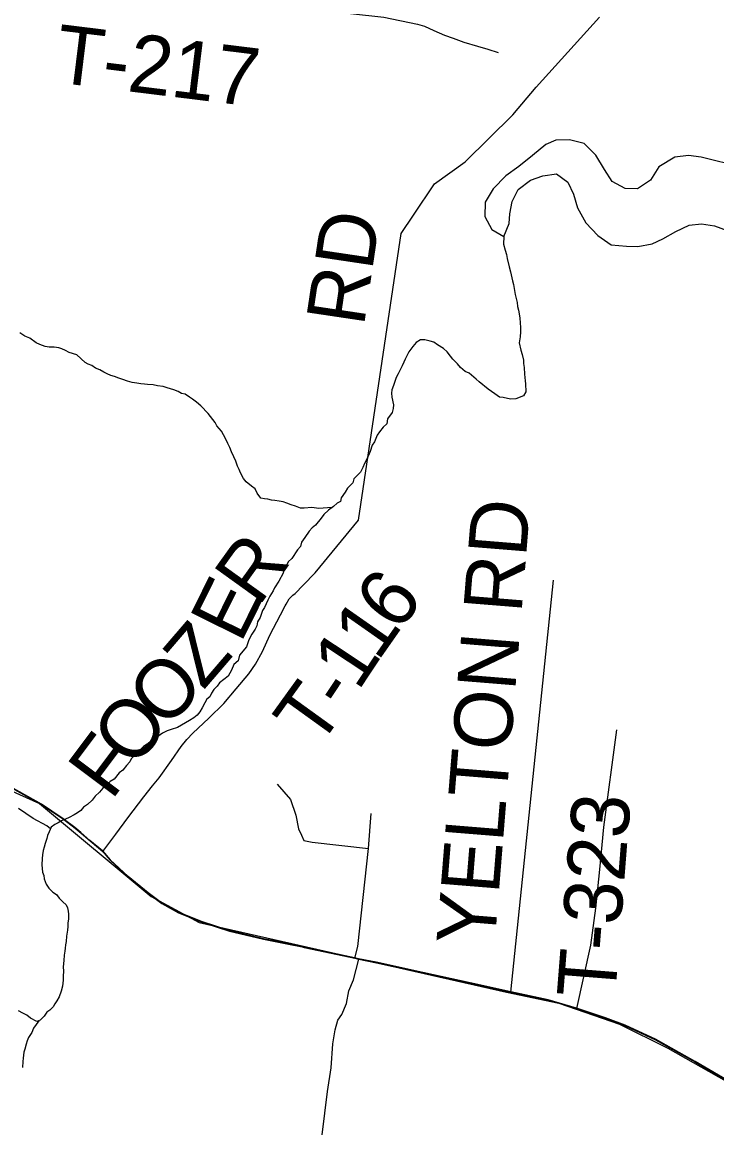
# Model space of a CAD drawing. Extents: x 0 to 39.3, y -3.9 to 22.
# Drawn here: x 6.949 to 7.624, y 16.679 to 17.777 of the extents above; entities that cross this region are included whole.
import ezdxf

# ---------------------------------------------------------------- set-up
doc = ezdxf.new("R2010")
doc.units = 0
for name, color, linetype in [('GM_X_Corporation', 7, 'Continuous'), ('GM_X_Major_Lake', 7, 'Continuous'), ('GM_X_Minor_River', 7, 'Continuous'), ('GM_X_Rail_Line', 7, 'Continuous'), ('GM_X_State_Route', 7, 'Continuous'), ('GM_X_Township_Road', 7, 'Continuous'), ('GM_X_Township_Road_Text', 7, 'Continuous')]:
    doc.layers.add(name, color=color, linetype=linetype)

msp = doc.modelspace()

# ---------------------------------------------------------------- linework, layer by layer
at = {"layer": 'GM_X_Corporation'}
for points in [[(6.9385, 17.0327), (6.9679, 17.0164), (6.9891, 17.0021), (7.0005, 16.9934), (7.0062, 16.9886), (7.0151, 16.9809), (7.0274, 16.9707), (7.0348, 16.962), (7.0525, 16.9457), (7.0718, 16.9299), (7.0848, 16.9201), (7.1011, 16.9111), (7.1248, 16.9016), (7.1506, 16.8932), (7.1841, 16.8853), (7.2066, 16.881), (7.2216, 16.8777), (7.2729, 16.8668), (7.2768, 16.8658), (7.294, 16.8623), (7.3392, 16.8523), (7.3929, 16.8408), (7.4249, 16.8337), (7.4386, 16.8306), (7.4615, 16.8258), (7.4891, 16.8177), (7.5171, 16.8082), (7.5364, 16.801), (7.5658, 16.7873), (7.6047, 16.7657), (7.6579, 16.7347)], [(7.6579, 16.7347), (7.6047, 16.7657), (7.5658, 16.7873), (7.5364, 16.801), (7.5171, 16.8082), (7.4891, 16.8177), (7.4615, 16.8258), (7.4386, 16.8306), (7.4249, 16.8337), (7.3929, 16.8408), (7.3392, 16.8523), (7.294, 16.8623), (7.2768, 16.8658), (7.2729, 16.8668), (7.2216, 16.8777), (7.2066, 16.881), (7.1841, 16.8853), (7.1506, 16.8932), (7.1248, 16.9016), (7.1011, 16.9111), (7.0848, 16.9201), (7.0718, 16.9299), (7.0525, 16.9457), (7.0348, 16.962), (7.0274, 16.9707), (7.0151, 16.9809), (7.0062, 16.9886), (7.0005, 16.9934), (6.9891, 17.0021), (6.9679, 17.0164), (6.9385, 17.0327)]]:
    msp.add_lwpolyline(points, dxfattribs=at)
at = {"layer": 'GM_X_Major_Lake'}
msp.add_lwpolyline([(7.6366, 17.6396), (7.6233, 17.6428), (7.6105, 17.6461), (7.5979, 17.6478), (7.5846, 17.6461), (7.5693, 17.6369), (7.5611, 17.6237), (7.5484, 17.6155), (7.5363, 17.6157), (7.5238, 17.6224), (7.5161, 17.6343), (7.5079, 17.6481), (7.4963, 17.6594), (7.4823, 17.663), (7.4687, 17.6629), (7.4591, 17.6585), (7.446, 17.6477), (7.4329, 17.6372), (7.4202, 17.6279), (7.4079, 17.6152), (7.4001, 17.6024), (7.3998, 17.5883), (7.4065, 17.5757), (7.4181, 17.569), (7.4233, 17.5815), (7.4242, 17.591), (7.4263, 17.6031), (7.4322, 17.6148), (7.4441, 17.6237), (7.4563, 17.6281), (7.4696, 17.6298), (7.4805, 17.622), (7.486, 17.6101), (7.49, 17.5967), (7.4981, 17.5822), (7.5097, 17.5698), (7.5228, 17.5608), (7.5376, 17.5594), (7.5487, 17.5593), (7.5627, 17.5617), (7.5731, 17.5668), (7.5857, 17.5739), (7.5988, 17.5801), (7.6106, 17.5814), (7.6234, 17.5793), (7.6382, 17.5738)], dxfattribs=at)
at = {"layer": 'GM_X_Minor_River'}
for points in [[(7.4181, 17.569), (7.418, 17.5616), (7.4195, 17.5555), (7.4209, 17.5513), (7.4216, 17.5475), (7.4234, 17.5395), (7.4248, 17.5345), (7.4266, 17.5257), (7.4276, 17.5223), (7.4294, 17.5124), (7.4311, 17.5047), (7.4315, 17.5009), (7.4325, 17.4971), (7.4332, 17.4936), (7.4339, 17.4895), (7.4345, 17.4803), (7.4345, 17.4761), (7.434, 17.4712), (7.4331, 17.4655), (7.4349, 17.4582), (7.436, 17.454), (7.4374, 17.4487), (7.4374, 17.4453), (7.4381, 17.4414), (7.4383, 17.435), (7.439, 17.4285), (7.4393, 17.4254), (7.4396, 17.4178), (7.4372, 17.4137), (7.4299, 17.4108), (7.4246, 17.4105), (7.4174, 17.4121), (7.414, 17.4126), (7.4095, 17.4157), (7.4031, 17.4204), (7.3941, 17.4274), (7.3911, 17.4301), (7.3844, 17.4359), (7.3806, 17.4375), (7.3761, 17.4414), (7.3731, 17.4449), (7.3686, 17.4495), (7.3664, 17.4526), (7.363, 17.4565), (7.3593, 17.4599), (7.3537, 17.4635), (7.3499, 17.4662), (7.3465, 17.467), (7.3412, 17.4682), (7.337, 17.4683), (7.3328, 17.4657), (7.3297, 17.462), (7.3258, 17.4567), (7.3222, 17.4496), (7.3207, 17.4465), (7.3191, 17.4431), (7.3152, 17.4352), (7.3132, 17.4318), (7.3108, 17.4239), (7.3092, 17.4197), (7.3088, 17.4163), (7.3091, 17.4125), (7.3108, 17.4049), (7.3104, 17.4015), (7.3096, 17.3977), (7.3049, 17.3913), (7.3041, 17.3864), (7.3006, 17.3834), (7.2971, 17.3789), (7.2948, 17.3755), (7.2924, 17.3691), (7.29, 17.3657), (7.288, 17.3596), (7.2849, 17.3521), (7.2825, 17.3479), (7.2809, 17.3442), (7.2786, 17.3396), (7.272, 17.3329), (7.2712, 17.3291), (7.2661, 17.3239), (7.2638, 17.3201), (7.2599, 17.3145), (7.2591, 17.3111), (7.256, 17.3092), (7.2522, 17.3062), (7.2475, 17.3025), (7.2429, 17.2984), (7.2402, 17.2947), (7.2347, 17.2879), (7.2317, 17.2853), (7.2286, 17.2819), (7.2243, 17.2759)], [(7.2508, 17.3052), (7.2381, 17.3042), (7.2312, 17.3051), (7.2236, 17.3045), (7.2202, 17.3045), (7.2153, 17.3065), (7.2111, 17.3077), (7.207, 17.3093), (7.2032, 17.3105), (7.1994, 17.3113), (7.1952, 17.3118), (7.1918, 17.3122), (7.1884, 17.3131), (7.185, 17.3135), (7.1816, 17.3143), (7.1779, 17.319), (7.176, 17.3232), (7.1723, 17.3259), (7.1674, 17.3302), (7.1648, 17.3333), (7.1618, 17.339), (7.1604, 17.3421), (7.1589, 17.3455), (7.1571, 17.3501), (7.1553, 17.3543), (7.1531, 17.3593), (7.1512, 17.3635), (7.1494, 17.3674), (7.1472, 17.3724), (7.1431, 17.3793), (7.1387, 17.3847), (7.1372, 17.3878), (7.1301, 17.3966), (7.123, 17.404), (7.1189, 17.4075), (7.1151, 17.4106), (7.1121, 17.4125), (7.108, 17.4153), (7.1042, 17.4161), (7.1012, 17.4181), (7.0967, 17.4197), (7.0936, 17.4205), (7.0902, 17.4217), (7.0865, 17.4229), (7.0808, 17.4237), (7.0766, 17.4246), (7.0713, 17.4247), (7.0682, 17.4251), (7.0648, 17.4255), (7.0607, 17.426), (7.0561, 17.4268), (7.0516, 17.4281), (7.047, 17.4297), (7.0433, 17.4309), (7.0391, 17.4325), (7.0353, 17.4337), (7.0319, 17.4352), (7.0285, 17.4368), (7.0248, 17.4392), (7.0206, 17.4408), (7.0169, 17.4435), (7.0135, 17.4447), (7.0104, 17.4463), (7.0022, 17.4536), (6.995, 17.4561), (6.9912, 17.458), (6.9879, 17.4596), (6.9848, 17.4604), (6.9803, 17.4613), (6.9753, 17.4613), (6.9715, 17.4618), (6.9663, 17.4638), (6.9629, 17.4654), (6.9565, 17.47), (6.9516, 17.472), (6.9467, 17.4752)], [(7.2243, 17.2759), (7.2212, 17.2714), (7.2203, 17.2672), (7.2172, 17.2639), (7.2118, 17.2556), (7.2083, 17.2522), (7.2063, 17.2481), (7.204, 17.2443), (7.2032, 17.2413), (7.1992, 17.2334), (7.1949, 17.227), (7.1937, 17.224), (7.1902, 17.2187), (7.1883, 17.2149), (7.1851, 17.2077), (7.1832, 17.2047), (7.1808, 17.1979), (7.1784, 17.1938), (7.1776, 17.19), (7.176, 17.1866), (7.1729, 17.1817), (7.1698, 17.1764), (7.1677, 17.1696), (7.1608, 17.1614), (7.1595, 17.1557), (7.1553, 17.1523), (7.1529, 17.1467), (7.1498, 17.141), (7.1413, 17.1343), (7.139, 17.1313), (7.1359, 17.128), (7.1335, 17.1242), (7.1319, 17.1208), (7.1289, 17.1186), (7.1269, 17.1148), (7.1245, 17.1099), (7.1222, 17.1061), (7.1195, 17.1028), (7.1164, 17.1002), (7.1122, 17.0976), (7.1003, 17.0909), (7.0941, 17.0891), (7.0903, 17.0877), (7.0857, 17.0855), (7.078, 17.0799), (7.0746, 17.0784), (7.0707, 17.0747), (7.0673, 17.0725), (7.0622, 17.0669), (7.0591, 17.0646), (7.0553, 17.0605), (7.0541, 17.0575), (7.0506, 17.0538), (7.0471, 17.0493), (7.0436, 17.0467), (7.0386, 17.0407), (7.0347, 17.0384), (7.032, 17.0351), (7.0278, 17.0317), (7.0243, 17.028), (7.0201, 17.0239), (7.0173, 17.0201), (7.0127, 17.016), (7.0089, 17.0134), (7.0061, 17.01), (7.0031, 17.0078), (6.9996, 17.006), (6.995, 17.0034), (6.9912, 17.0015), (6.9873, 17.0001), (6.9843, 16.9982), (6.9808, 16.9964), (6.9773, 16.9938), (6.9754, 16.9893), (6.9738, 16.9859), (6.973, 16.9828), (6.9714, 16.9779), (6.9706, 16.9745), (6.9697, 16.9711), (6.9689, 16.9669), (6.9685, 16.9635), (6.9684, 16.9571), (6.969, 16.9502), (6.9701, 16.9468), (6.9704, 16.9437), (6.9726, 16.9383), (6.9752, 16.9345), (6.9789, 16.9306), (6.9827, 16.9283), (6.9853, 16.9248), (6.9887, 16.9213), (6.992, 16.9182), (6.9931, 16.9152), (6.9938, 16.9121), (6.9942, 16.9091), (6.9941, 16.9045), (6.9936, 16.9003), (6.9936, 16.8973), (6.9931, 16.8935), (6.9923, 16.8878), (6.9918, 16.8825)], [(6.9766, 16.9921), (6.9732, 16.9952), (6.9597, 17.0023), (6.9454, 17.0121)], [(6.9918, 16.8825), (6.9914, 16.8794), (6.9909, 16.876), (6.9905, 16.873), (6.9901, 16.8692), (6.9896, 16.8642), (6.9891, 16.8578), (6.9894, 16.8536), (6.989, 16.8487), (6.9889, 16.8449), (6.9884, 16.8392), (6.9872, 16.8342), (6.9852, 16.8286), (6.9829, 16.8248), (6.9809, 16.8218), (6.9793, 16.8188), (6.9762, 16.8158), (6.9732, 16.8136), (6.9704, 16.8098), (6.9666, 16.8061), (6.9635, 16.8046), (6.9571, 16.8078), (6.9537, 16.8109), (6.9496, 16.8128), (6.9454, 16.8152)], [(6.9652, 16.8054), (6.96, 16.7982), (6.9584, 16.794), (6.9553, 16.7891), (6.9541, 16.7857), (6.9529, 16.7827), (6.9517, 16.7778), (6.9508, 16.7748), (6.95, 16.7691), (6.9499, 16.7657), (6.9495, 16.76)]]:
    msp.add_lwpolyline(points, dxfattribs=at)
at = {"layer": 'GM_X_Rail_Line'}
msp.add_lwpolyline([(5.9832, 17.5323), (6.1809, 17.4246), (6.6945, 17.1424), (6.8149, 17.0848), (6.966, 17.0168), (7.0746, 16.9262), (7.1215, 16.9012), (7.4207, 16.8333), (7.4717, 16.8224), (7.5307, 16.8022), (7.5779, 16.7788), (7.8941, 16.5999)], dxfattribs=at)
at = {"layer": 'GM_X_State_Route'}
for p, q in [((7.2238, 16.8768), (7.2731, 16.8663)), ((7.2731, 16.8663), (7.2771, 16.8652))]:
    msp.add_line(p, q, dxfattribs=at)
for points in [[(6.8996, 17.0497), (6.9116, 17.0444), (6.9388, 17.0322), (6.9681, 17.0159), (6.9893, 17.0016), (7.0008, 16.9929), (7.0065, 16.9881), (7.0153, 16.9804), (7.0277, 16.9702)], [(7.0277, 16.9702), (7.035, 16.9615), (7.0527, 16.9452), (7.072, 16.9294), (7.0851, 16.9196), (7.1014, 16.9106), (7.125, 16.9011), (7.1509, 16.8927), (7.1843, 16.8848), (7.2069, 16.8804), (7.2218, 16.8772), (7.2238, 16.8768)], [(7.2771, 16.8652), (7.2942, 16.8618), (7.3267, 16.8546)], [(7.3267, 16.8546), (7.3395, 16.8518), (7.3931, 16.8403), (7.4251, 16.8332)], [(7.4251, 16.8332), (7.4388, 16.83), (7.4617, 16.8253), (7.4893, 16.8172)], [(7.4893, 16.8172), (7.5174, 16.8077), (7.5366, 16.8005), (7.566, 16.7868), (7.6049, 16.7652), (7.6581, 16.7342), (7.7027, 16.7073), (7.7084, 16.7038), (7.746, 16.6845), (7.7537, 16.6804)]]:
    msp.add_lwpolyline(points, dxfattribs=at)
at = {"layer": 'GM_X_Township_Road'}
msp.add_line((7.4251, 16.8332), (7.4665, 17.2345), dxfattribs=at)
for points in [[(6.9501, 17.8209), (7.1548, 17.7982), (7.1802, 17.7959), (7.3014, 17.7825), (7.3342, 17.7757), (7.341, 17.7736), (7.35, 17.7696), (7.3605, 17.7651), (7.3687, 17.7619), (7.3792, 17.7582), (7.3924, 17.7544), (7.4026, 17.7515), (7.4127, 17.7482)], [(7.3301, 17.5896), (7.3506, 17.6203), (7.3807, 17.6416), (7.427, 17.6874), (7.4497, 17.7142), (7.5114, 17.7824)], [(7.2127, 17.2196), (7.2149, 17.2215), (7.2227, 17.2296), (7.2344, 17.2415), (7.2767, 17.2928), (7.3182, 17.5718), (7.3301, 17.5896)], [(7.1096, 17.0792), (7.1154, 17.0855), (7.131, 17.0999), (7.1454, 17.1144), (7.1575, 17.1285), (7.17, 17.1433), (7.1763, 17.1527), (7.1831, 17.165), (7.1903, 17.1808), (7.2007, 17.2006), (7.2054, 17.2095), (7.2063, 17.2111), (7.2091, 17.2163), (7.2127, 17.2196)], [(7.4893, 16.8172), (7.503, 16.8789), (7.5078, 16.9149), (7.5118, 16.9527), (7.5157, 16.9938), (7.5281, 17.0886)], [(7.0808, 17.0398), (7.0826, 17.042), (7.0946, 17.0588), (7.1038, 17.0725), (7.1096, 17.0792)], [(7.0277, 16.9702), (7.0402, 16.987), (7.0521, 17.0031), (7.0676, 17.0235), (7.0761, 17.0341), (7.0808, 17.0398)], [(7.1975, 17.0357), (7.2105, 17.0209), (7.2155, 17.0056), (7.2181, 16.9922), (7.221, 16.9861), (7.2234, 16.9808), (7.2317, 16.9792), (7.2865, 16.9731)], [(7.2731, 16.8663), (7.2759, 16.8778), (7.2865, 16.9731), (7.2889, 17.0073)], [(7.2414, 16.6944), (7.2466, 16.7365), (7.2499, 16.7595), (7.2518, 16.7828), (7.2541, 16.7965), (7.2566, 16.8059), (7.2604, 16.8116), (7.2649, 16.8222), (7.2674, 16.8344), (7.2719, 16.8451), (7.2771, 16.8652)]]:
    msp.add_lwpolyline(points, dxfattribs=at)

# ---------------------------------------------------------------- texts
at = {"layer": 'GM_X_Township_Road_Text'}
for s, height, rotation, p in [('T-217', 0.05682, 352.9798, (6.9793, 17.7193)), ('RD', 0.05682, 81.5194, (7.2818, 17.4805)), ('YELTON RD', 0.05682, 85.368, (7.4091, 16.8774)), ('R', 0.0568, 54.2745, (7.1794, 17.2078)), ('6', 0.0568, 52.5993, (7.3151, 17.1825)), ('E', 0.0568, 63.6514, (7.1618, 17.1718)), ('1', 0.0568, 55.0007, (7.2954, 17.1544)), ('Z', 0.0568, 49.3252, (7.1255, 17.1266)), ('1', 0.0568, 56.4687, (7.2763, 17.1255)), ('O', 0.0568, 45.7367, (7.088, 17.088)), ('T', 0.0568, 54.2067, (7.2372, 17.0695)), ('-', 0.0568, 56.4869, (7.2634, 17.106)), ('O', 0.0568, 52.7483, (7.0589, 17.0496)), ('F', 0.0568, 53.131, (7.036, 17.019)), ('T-323', 0.05682, 85.4926, (7.5264, 16.8261))]:
    msp.add_text(s, height=height, rotation=rotation, dxfattribs=at).set_placement(p)

doc.saveas('drawing.dxf')
